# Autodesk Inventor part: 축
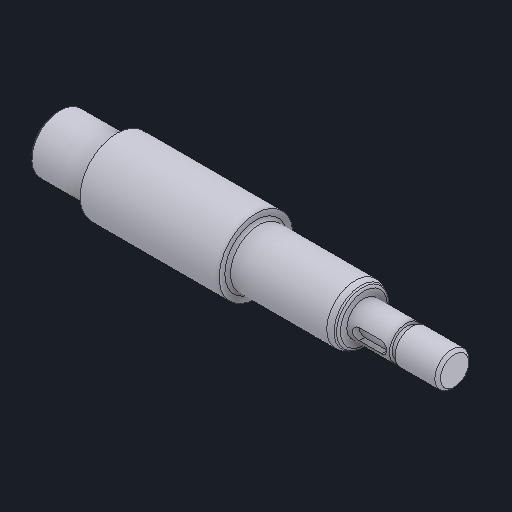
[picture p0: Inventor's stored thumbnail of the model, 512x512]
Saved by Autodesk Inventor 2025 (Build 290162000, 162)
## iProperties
Created: 2025-08
Part Number: 축
Material: 강철, 연강
Document SubType Name: Modeling
Designer: infra17
Density: 7.86 g/cm^3
Appearance: 기본값
Author: jhkim
Sending System: Autodesk Inventor 2026
Preprocessor: ST-DEVELOPER v20.1
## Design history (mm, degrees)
feature "솔리드2"
node "솔리드1"
